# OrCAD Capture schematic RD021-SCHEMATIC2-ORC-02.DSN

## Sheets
1 5: size A3
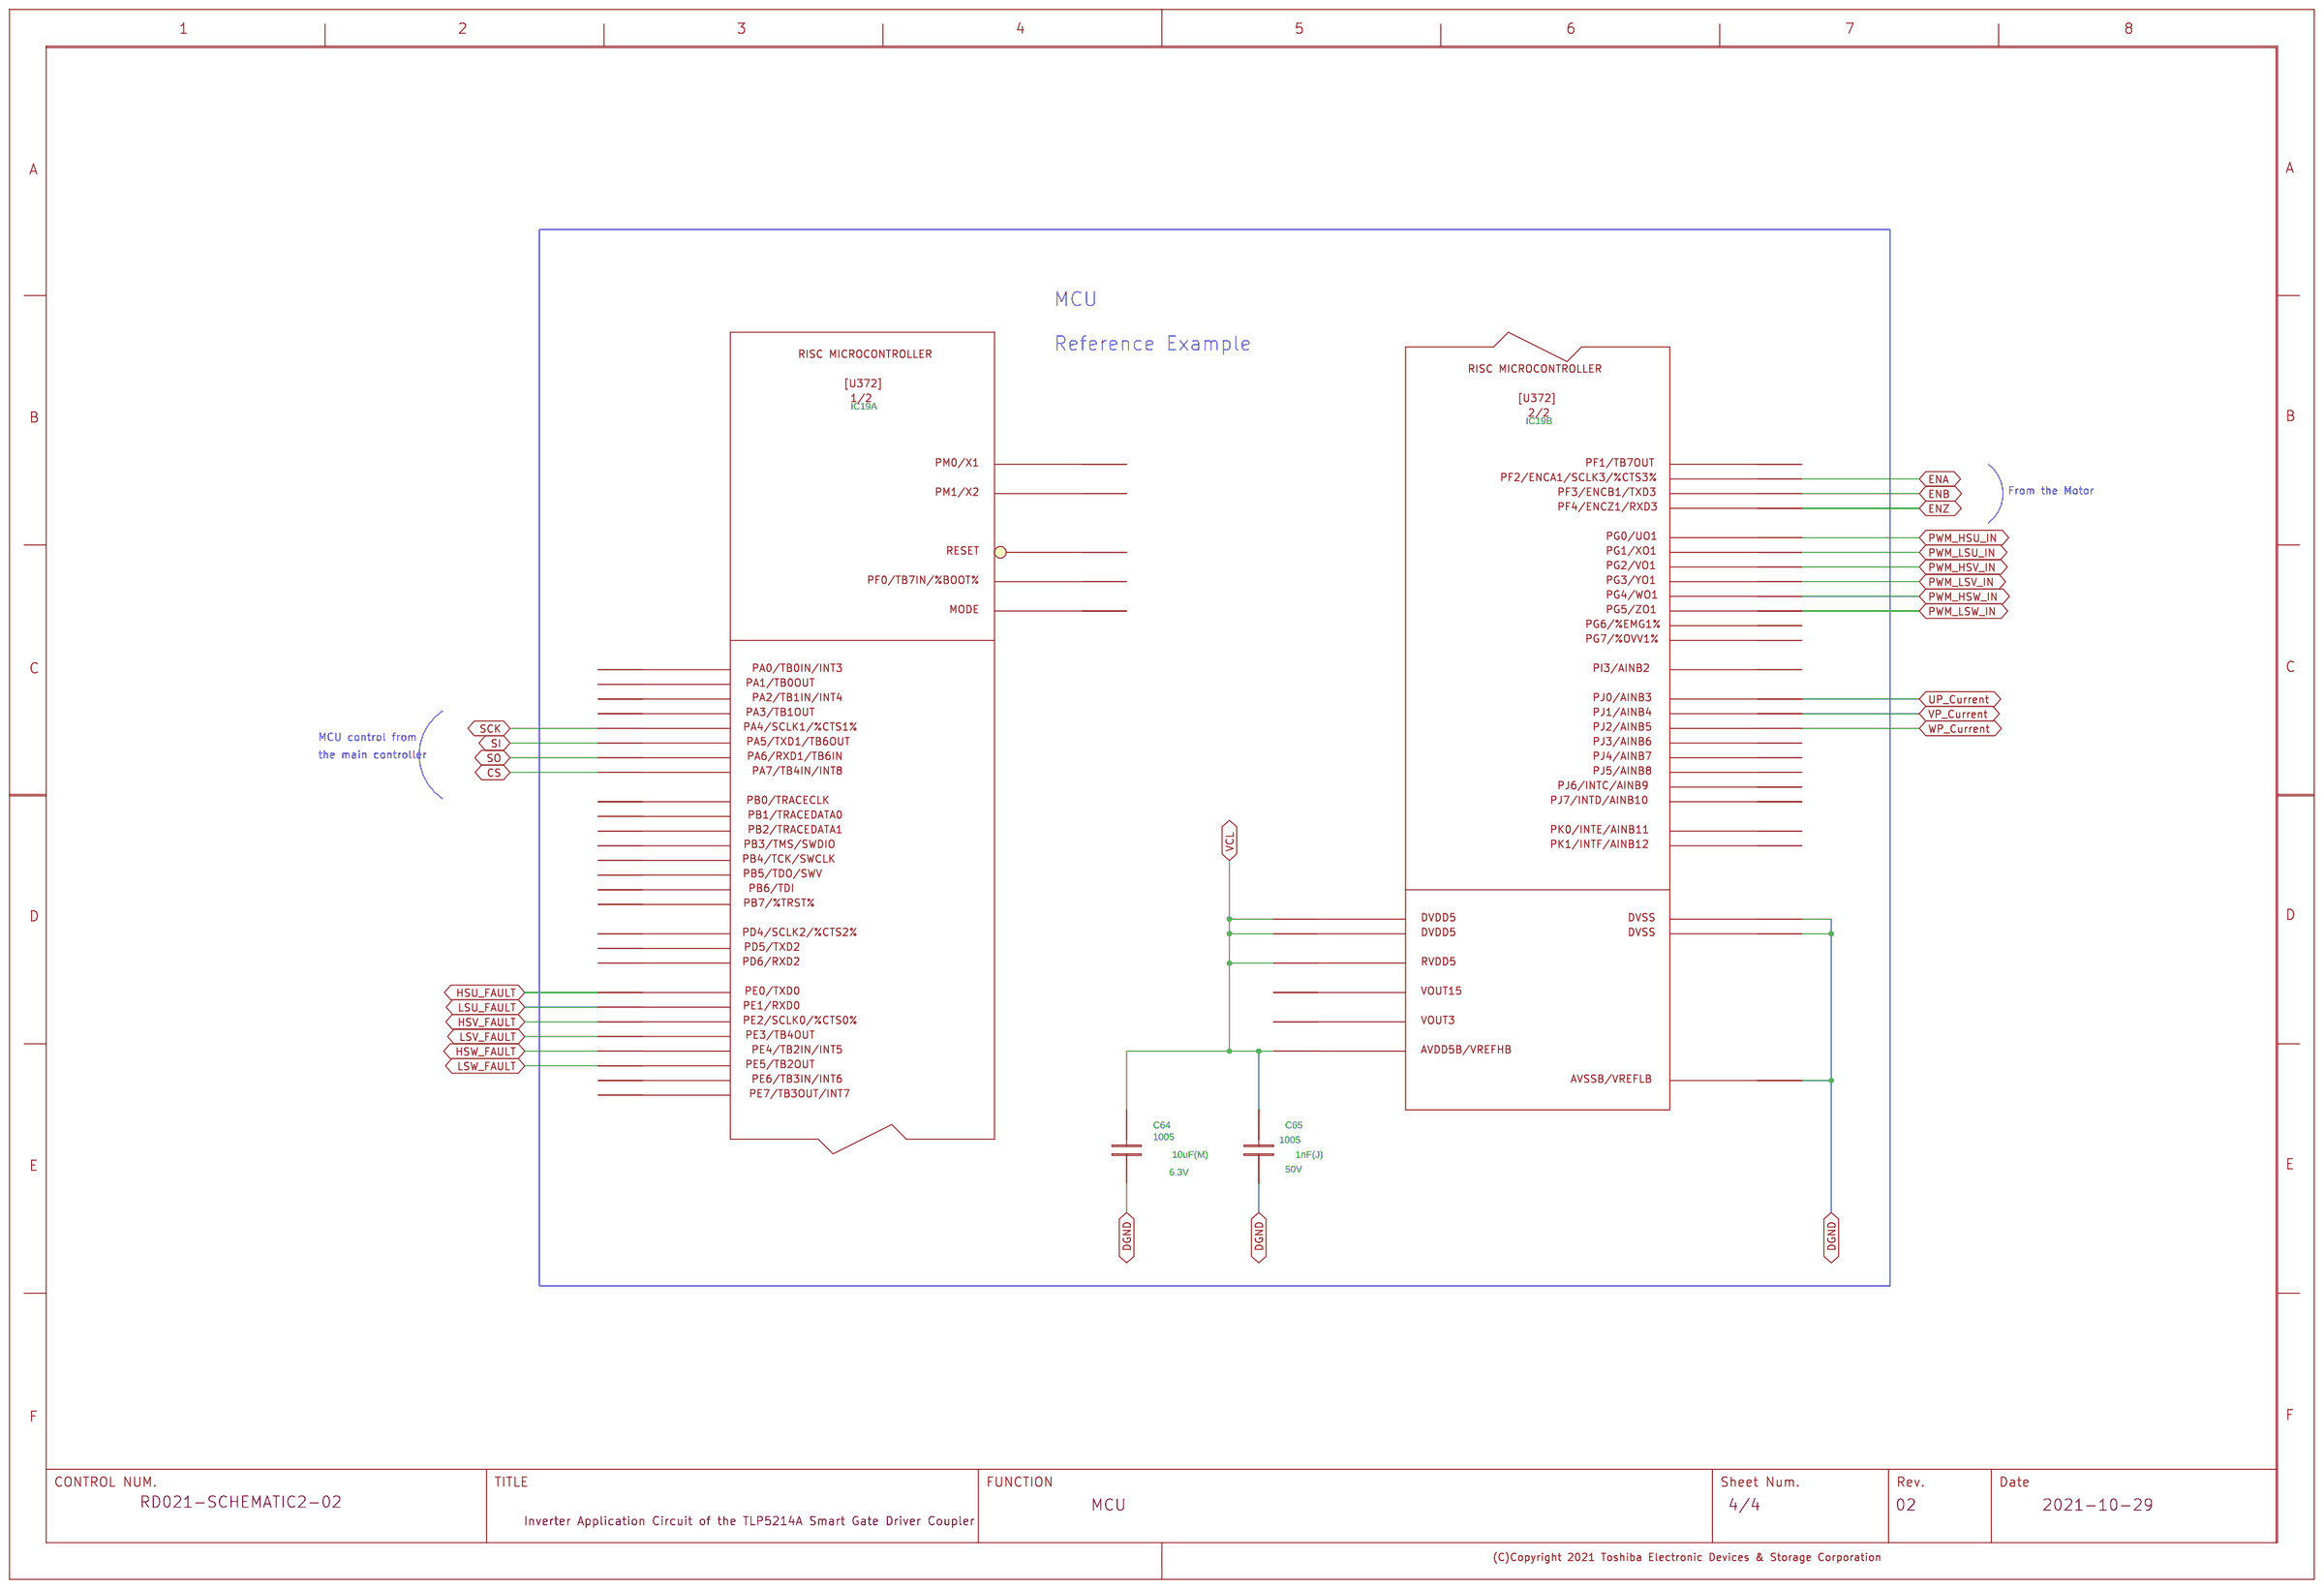
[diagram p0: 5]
2 4: size A3
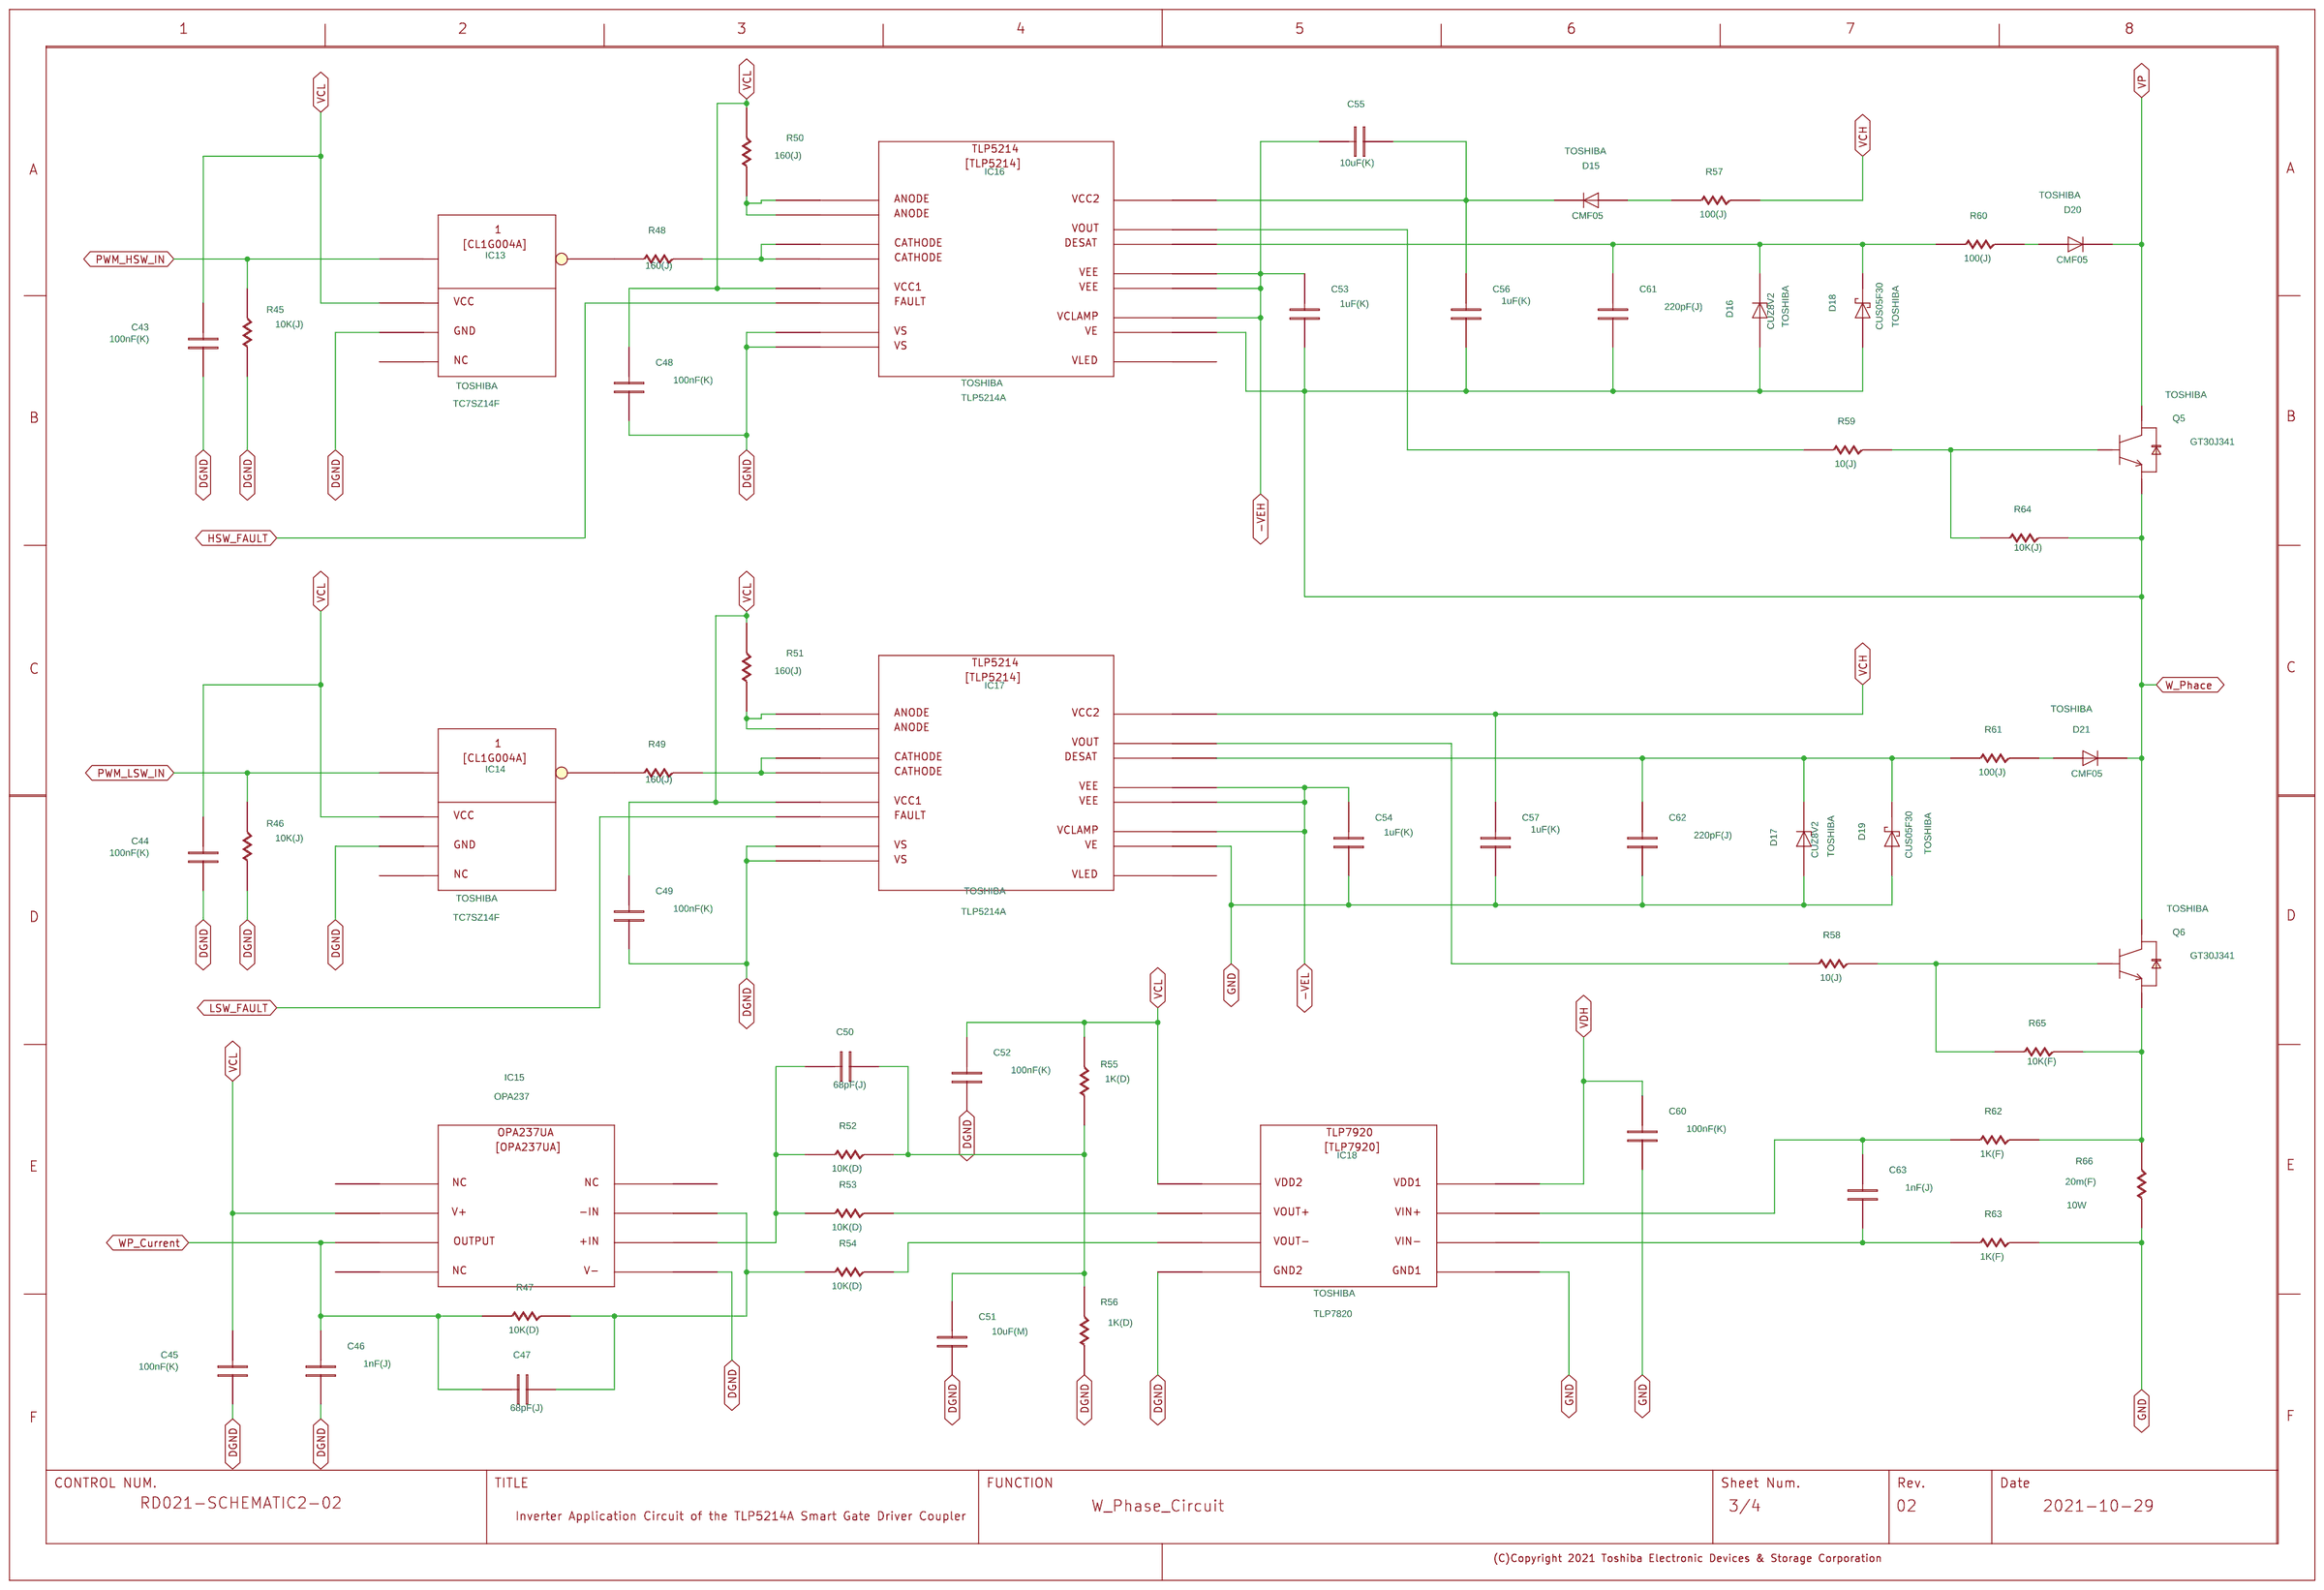
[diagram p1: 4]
3 3: size A3
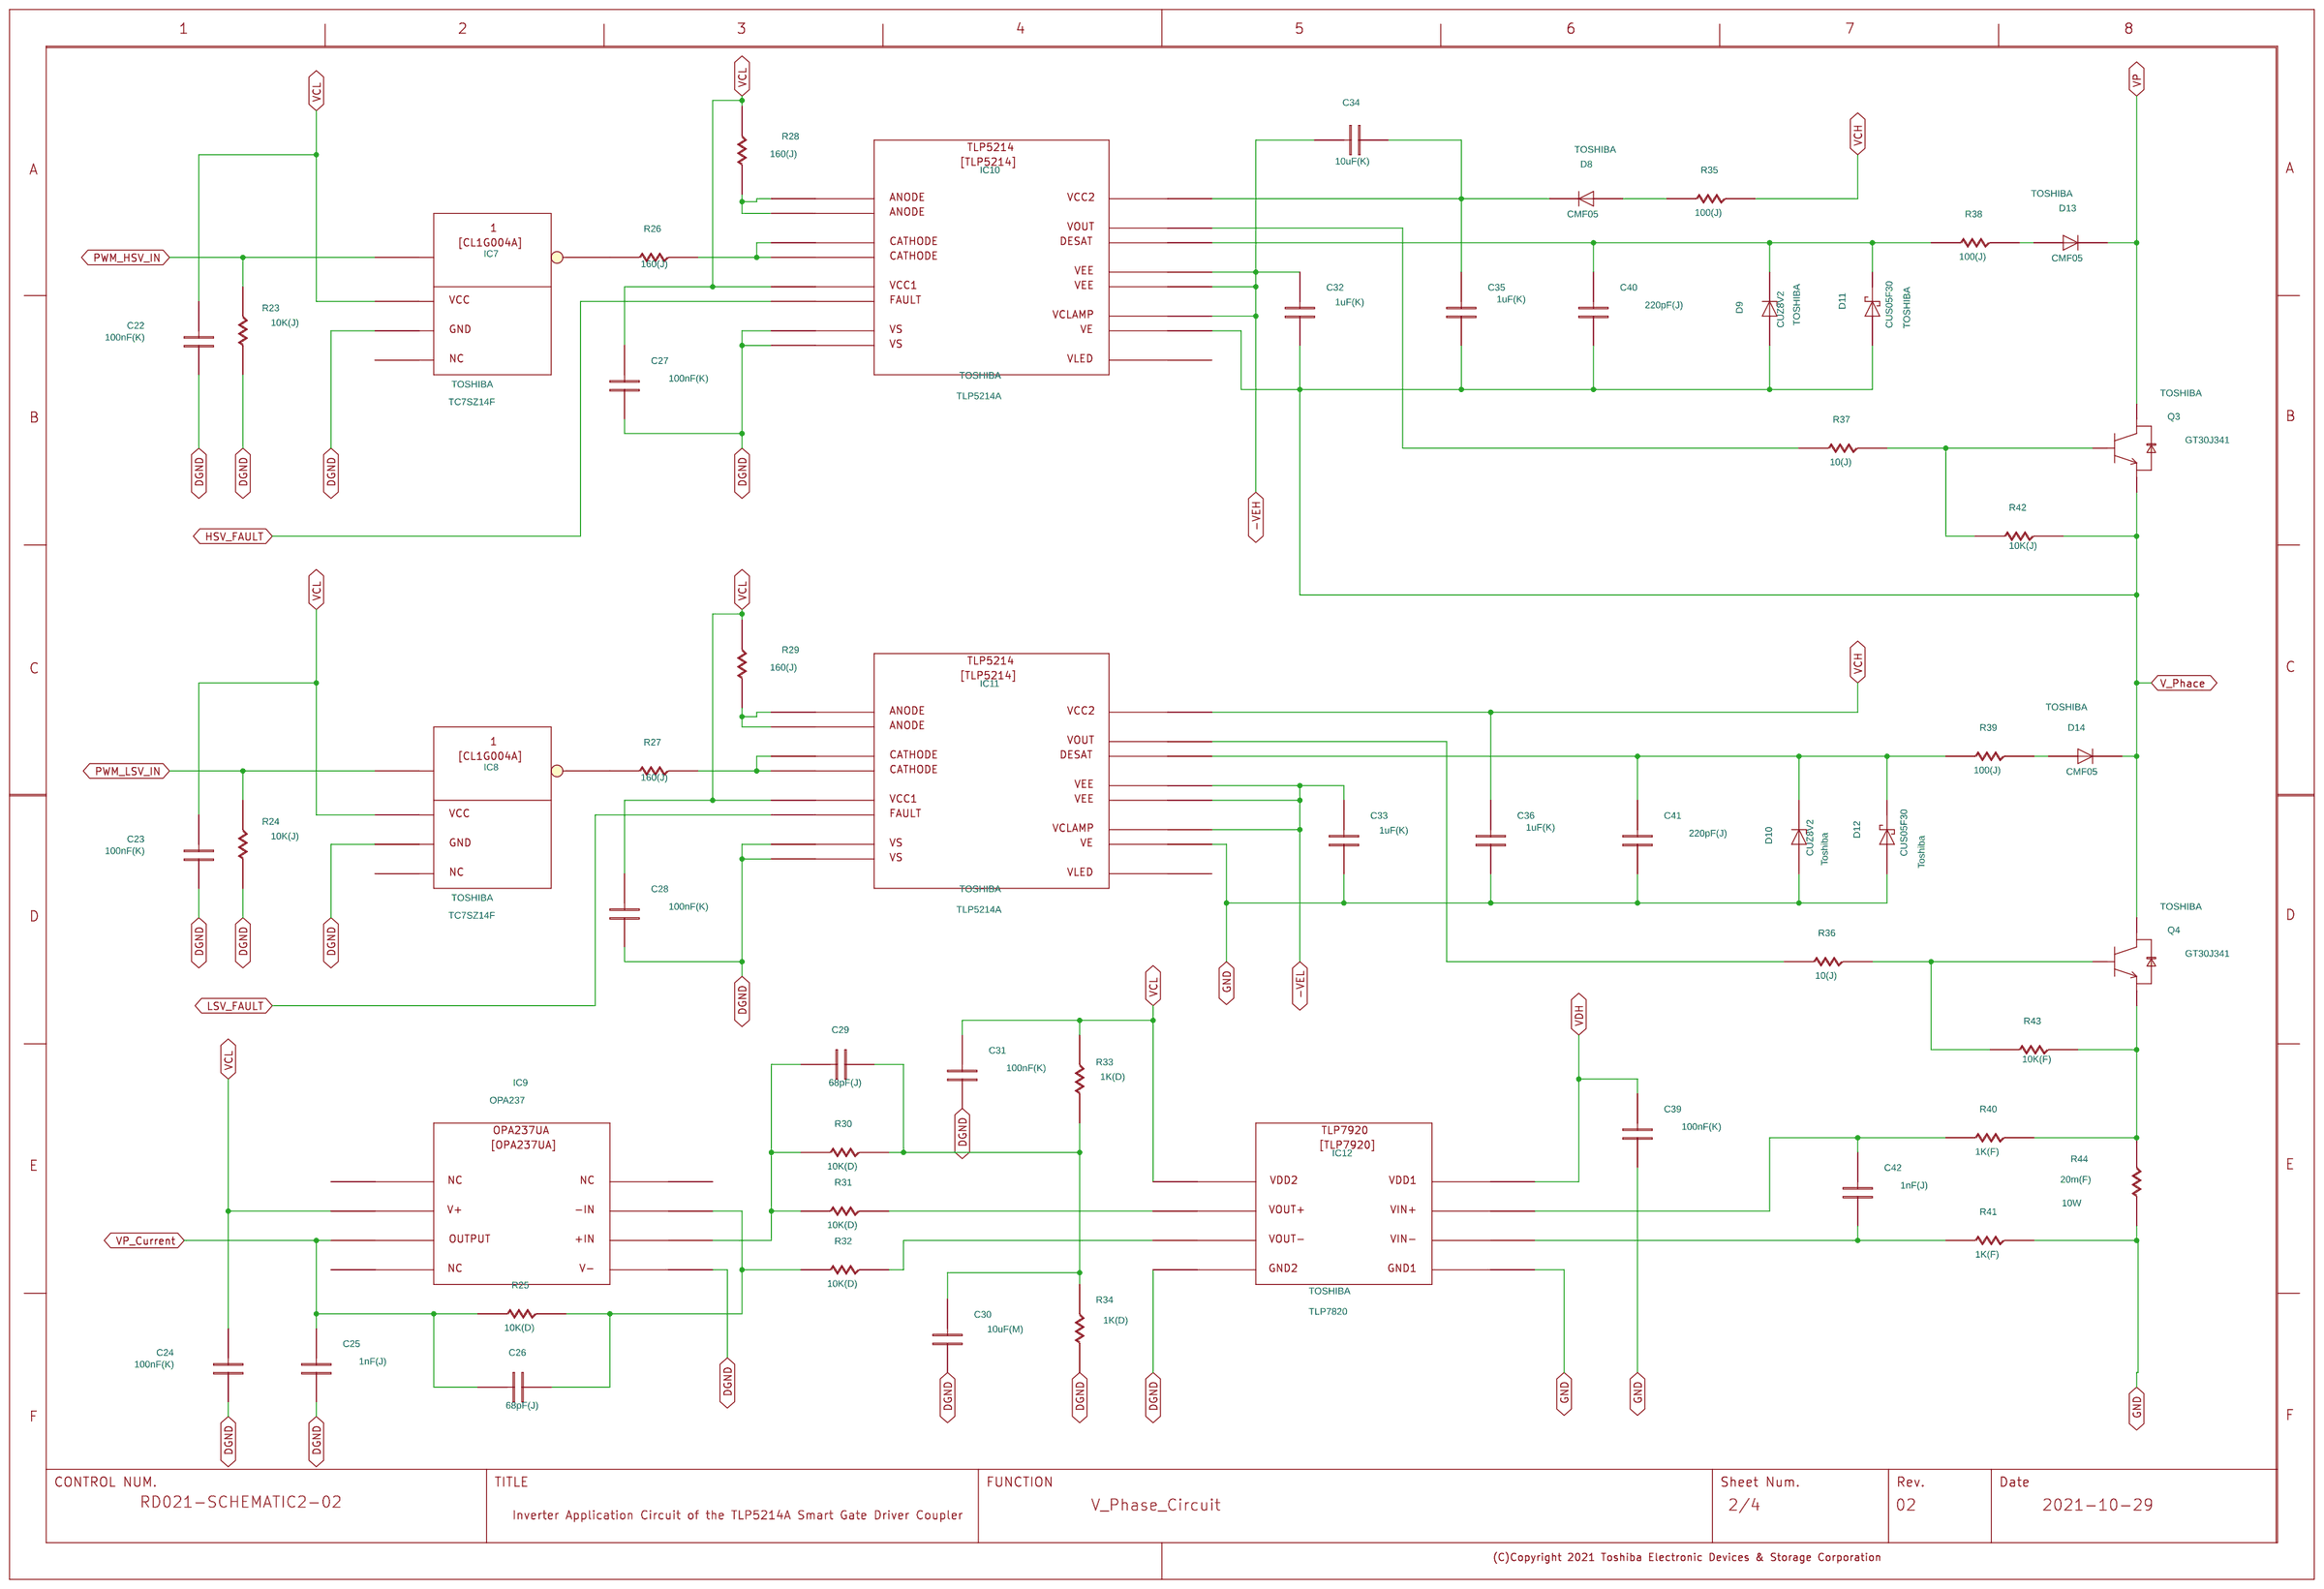
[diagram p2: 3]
4 2: size A3
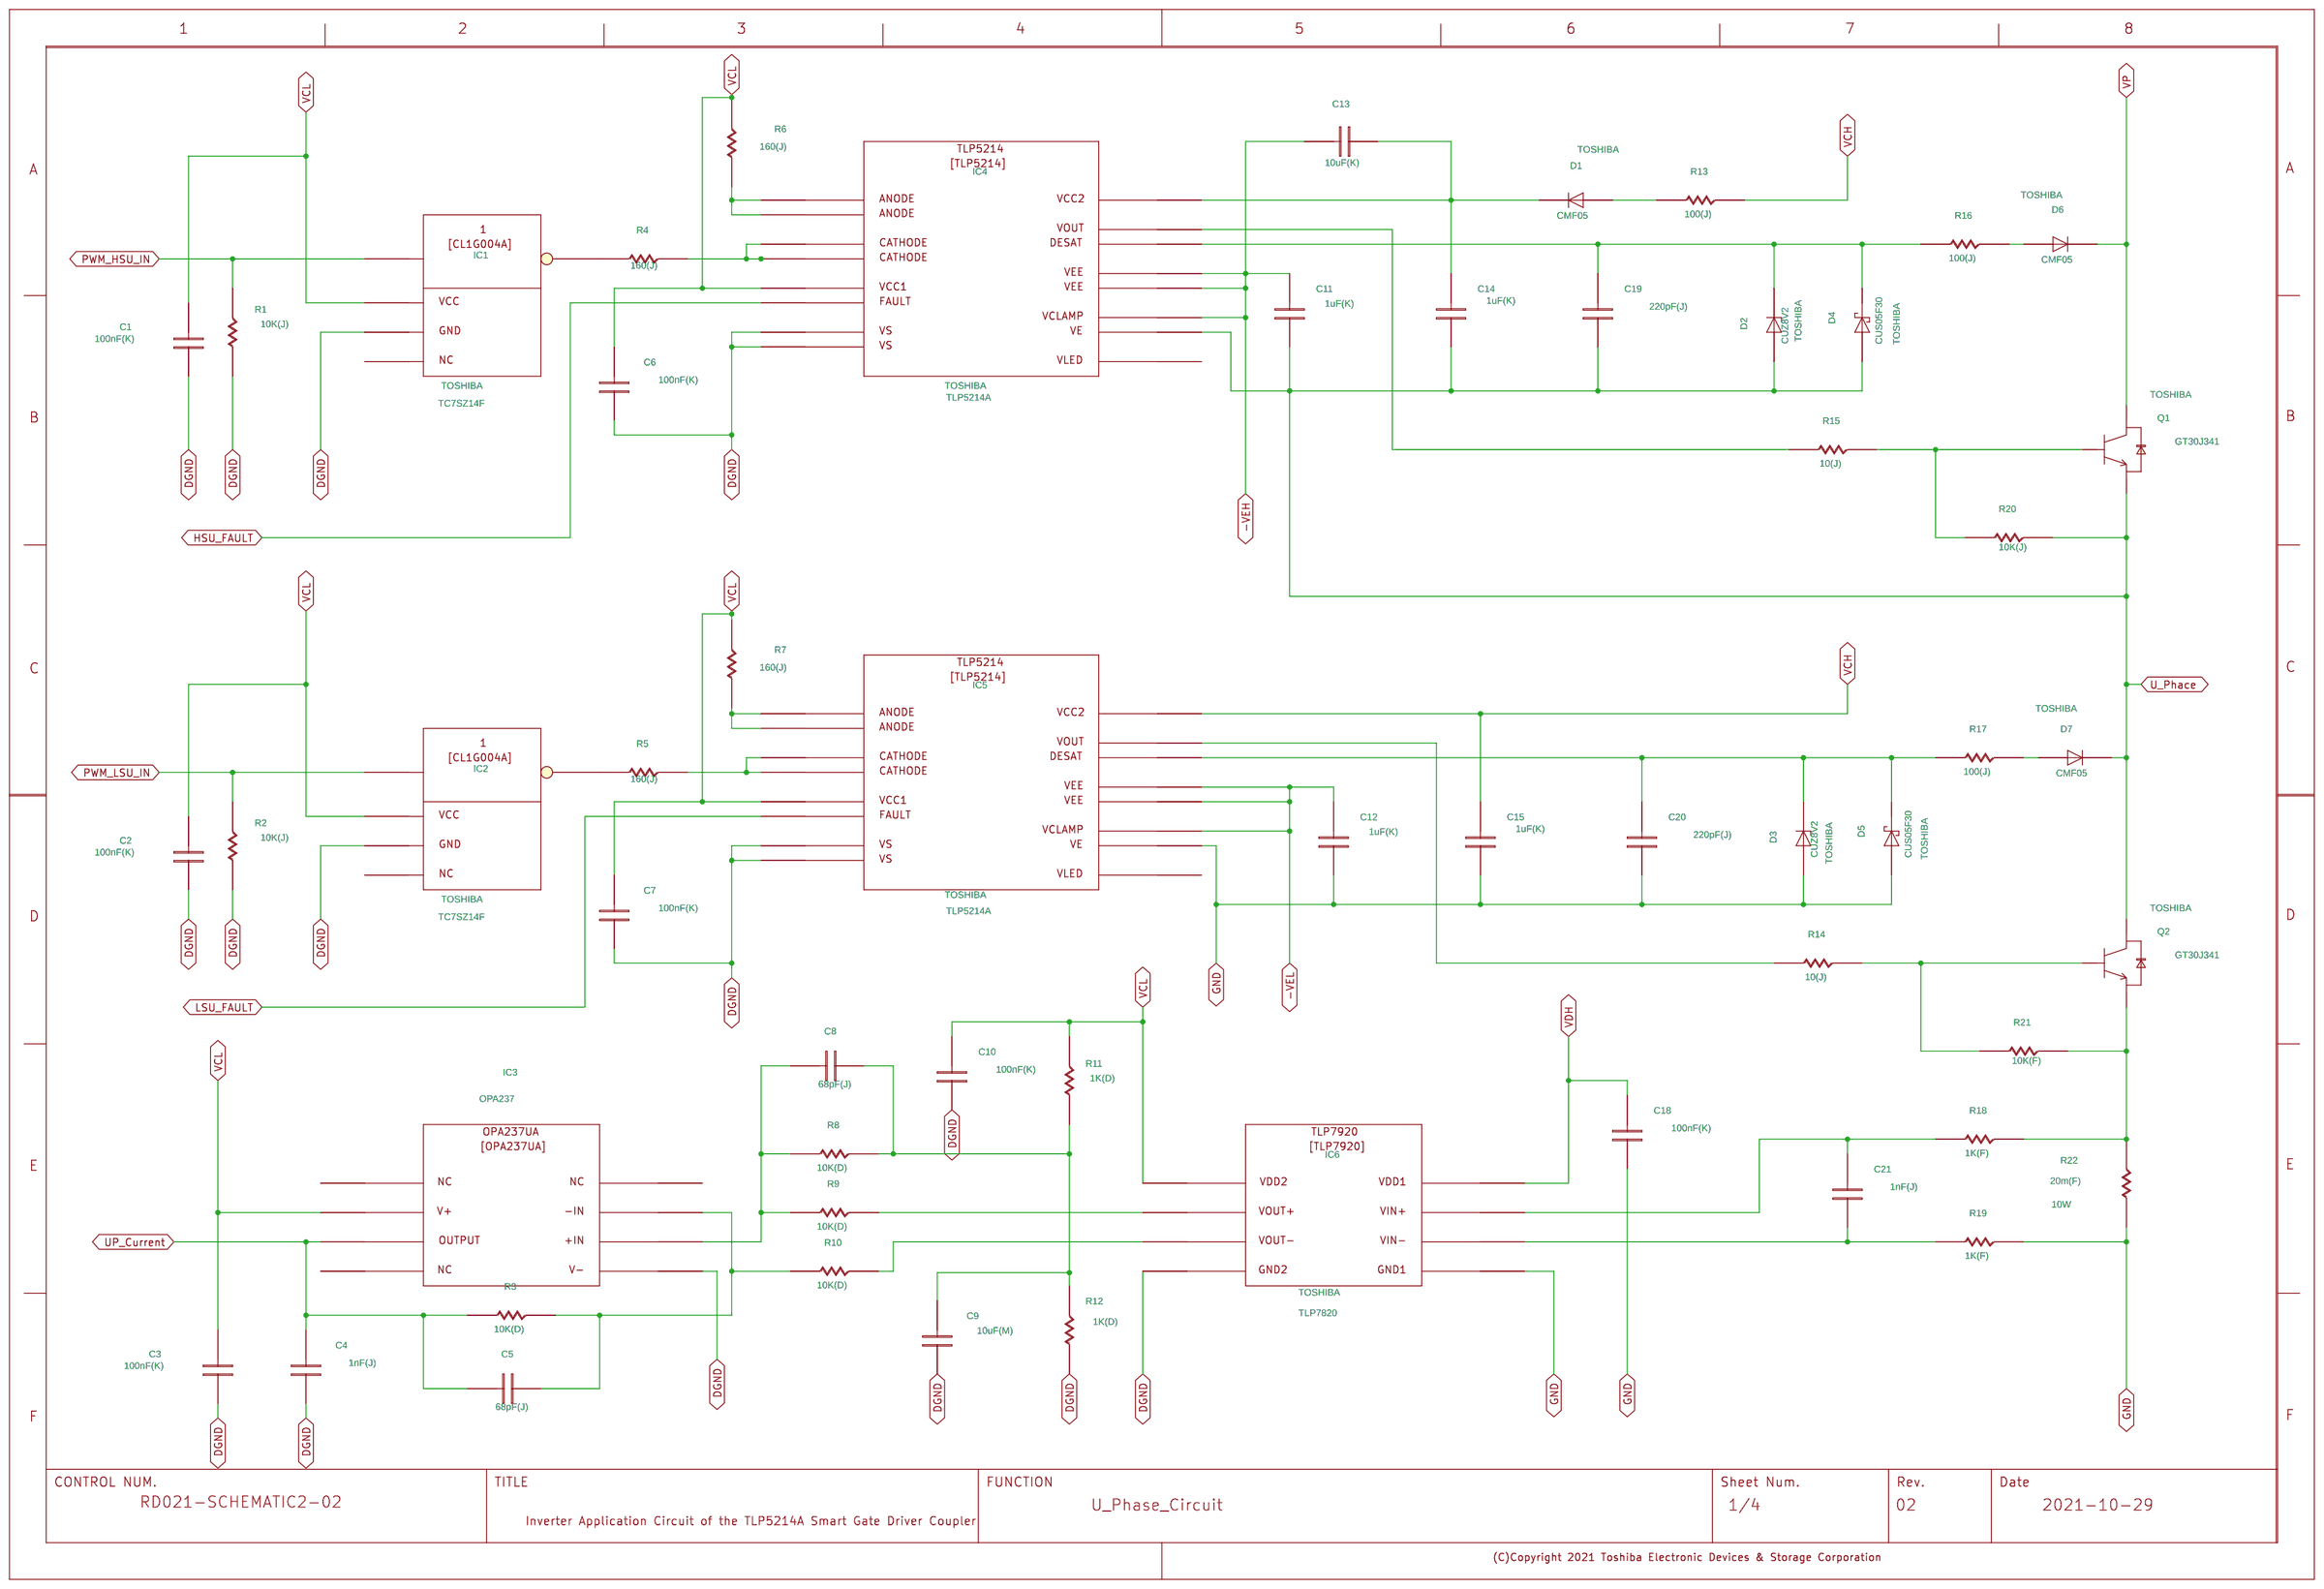
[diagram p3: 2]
5 1
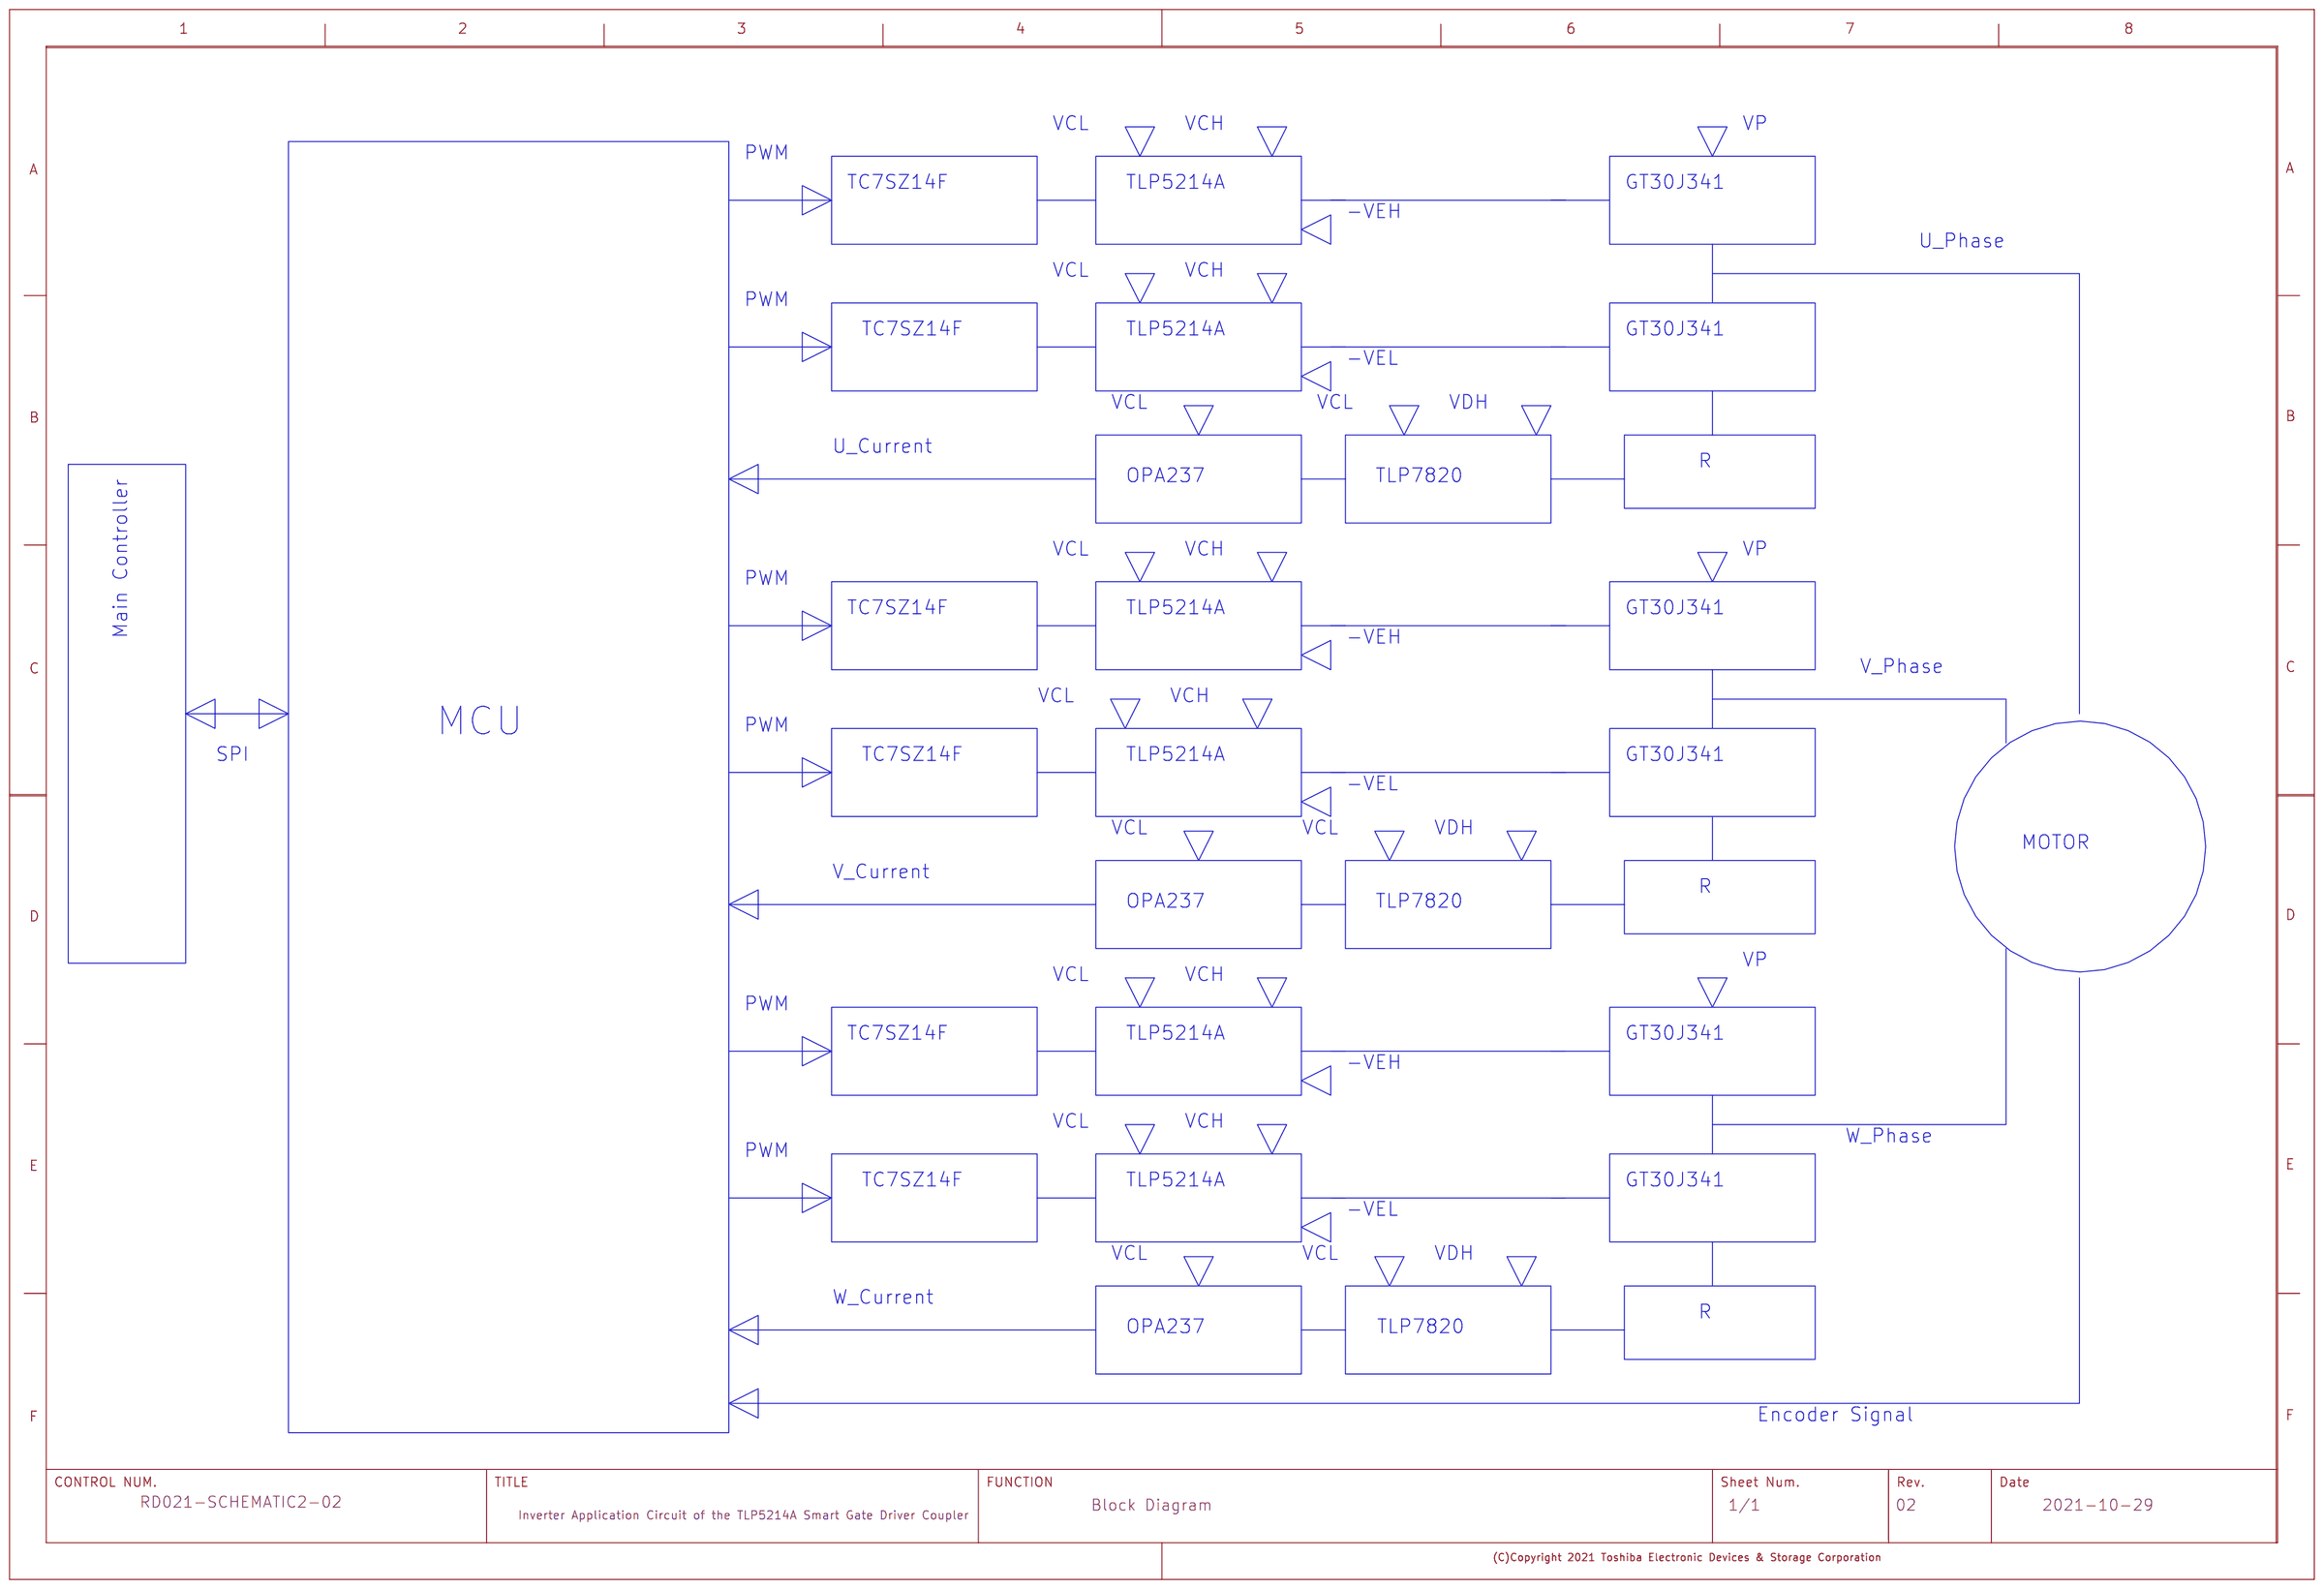
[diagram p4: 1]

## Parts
sheet 1
U?#4  WAKU_DEF100
sheet 2
C1  C
C2  C
C3  C
C4  C
C5  C
C6  C
C7  C
C8  C
C9  C
C10  C
C11  C
C12  C
C13  C
C14  C
C15  C
C18  C
C19  C
C20  C
C21  C
D1  D
D2  ZD
D3  ZD
D4  SBD
D5  SBD
D6  D
D7  D
IC1  CL1G004A
IC2  CL1G004A
IC3  S-OPA237UA
IC4  S-TLP5214
IC5  S-TLP5214
IC6  S-TLP7920
Q1  S-GT30J341
Q2  S-GT30J341
R1  R
R2  R
R3  R
R4  R
R5  R
R6  R
R7  R
R8  R
R9  R
R10  R
R11  R
R12  R
R13  R
R14  R
R15  R
R16  R
R17  R
R18  R
R19  R
R20  R
R21  R
R22  R
U?#3  WAKU_DEF100
sheet 3
C22  C
C23  C
C24  C
C25  C
C26  C
C27  C
C28  C
C29  C
C30  C
C31  C
C32  C
C33  C
C34  C
C35  C
C36  C
C39  C
C40  C
C41  C
C42  C
D8  D
D9  ZD
D10  ZD
D11  SBD
D12  SBD
D13  D
D14  D
IC7  CL1G004A
IC8  CL1G004A
IC9  S-OPA237UA
IC10  S-TLP5214
IC11  S-TLP5214
IC12  S-TLP7920
Q3  S-GT30J341
Q4  S-GT30J341
R23  R
R24  R
R25  R
R26  R
R27  R
R28  R
R29  R
R30  R
R31  R
R32  R
R33  R
R34  R
R35  R
R36  R
R37  R
R38  R
R39  R
R40  R
R41  R
R42  R
R43  R
R44  R
U?#2  WAKU_DEF100
sheet 4
C43  C
C44  C
C45  C
C46  C
C47  C
C48  C
C49  C
C50  C
C51  C
C52  C
C53  C
C54  C
C55  C
C56  C
C57  C
C60  C
C61  C
C62  C
C63  C
D15  D
D16  ZD
D17  ZD
D18  SBD
D19  SBD
D20  D
D21  D
IC13  CL1G004A
IC14  CL1G004A
IC15  S-OPA237UA
IC16  S-TLP5214
IC17  S-TLP5214
IC18  S-TLP7920
Q5  S-GT30J341
Q6  S-GT30J341
R45  R
R46  R
R47  R
R48  R
R49  R
R50  R
R51  R
R52  R
R53  R
R54  R
R55  R
R56  R
R57  R
R58  R
R59  R
R60  R
R61  R
R62  R
R63  R
R64  R
R65  R
R66  R
U?#1  WAKU_DEF100
sheet 5
C64  C
C65  C
IC19  U372_1  (sections A,B)
U?#5  WAKU_DEF100

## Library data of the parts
U?#4 = WAKU_DEF100_0: COMPONENTTYPE: 2; DATE: 2021-10-29; DRAWINGNUMBER: RD021-SCHEMATIC2-02; FUNCTION: Block Diagram; REVISION: 02; SHEETNUMBER: 1/1; TITLE: Inverter Application Circuit of the TLP5214A Smart Gate Driver Coupler; UPDATEDATE: 2018/06/19; UPDATETIME: 16:54:06; UPDATEUSER: g4302510
C1-C3 C6 C7 C10 C18 C22-C24 C27 C28 C31 C39 C43-C45 C48 C49 C52 C60 = C: ADSCNVFLAG: ON; ALLGREEN: 0:O[; CAPACITANCETOLE: K; CDBNAME: K0302394; CDMASTERCADCELG: KC0008; COMP: K0302394; COMPONENTNAME: K0302394_package; COMPONENTTYPE: 4; FNAPPROVALRESUG: 5:bè(KR[h); FNCANCELLATIONG: 0:Žg—p‰Â; FNENVIRONMANTRG: 0:Žg—p–³; FNLEADFREETHET1GT2GMCTH1: 3_2_N; FUNCN: K0302394; GANSWERREV: 9; GCOUNT: 1; ICX_PART_MODEL: CON_100N; MAXGCOUNT: 1; NOMINALCAPACITA: 100n; OUMECLASSIFICATION: ƒZƒ‰ƒ~ƒbƒNƒRƒ“ƒfƒ“ƒT; PMPRODUCTSTYPEG: HD1; QUADMODEL: CON_100N; RATEDVOLTAGE: 50; SIZECODESMD: 1608; SQ_PART_MODEL: CON_100N; VAL1: 100nF(K); VAL2: 50V
C4 C21 C25 C42 C46 C63 = C: ADSCNVFLAG: ON; ALLGREEN: N:¢²¸; CAPACITANCETOLE: J; CDBNAME: K0301613; CDMASTERCADCELG: KC0008; COMP: K0301613; COMPONENTNAME: K0301613_package; COMPONENTTYPE: 4; FNAPPROVALRESUG: 5:bè(KR[h); FNCANCELLATIONG: 0:Žg—p‰Â; FNENVIRONMANTRG: N:¢²¸; FNLEADFREETHET1GT2GMCTH1: N_N_N; FUNCN: K0301613; GCOUNT: 1; ICX_PART_MODEL: CON_1N; MAXGCOUNT: 1; NOMINALCAPACITA: 1n; OUMECLASSIFICATION: ƒZƒ‰ƒ~ƒbƒNƒRƒ“ƒfƒ“ƒT; PMPRODUCTSTYPEG: DME; QUADMODEL: CON_1N; RATEDVOLTAGE: 50; SIZECODESMD: 1608; SQ_PART_MODEL: CON_1N; VAL1: 1nF(J); VAL2: 50V
C5 C8 C26 C29 C47 C50 = C: ADSCNVFLAG: ON; ADSCOMPONENTNAME: C_1005; ADSMODELNAME: s_GRM1552C1H680JA01D; ALLGREEN: N:¢²¸; CAPACITANCETOLE: J; CDBNAME: GDM030002286; CDMASTERCADCELG: KC0005; COMP: GDM030002286; COMPONENTNAME: GDM030002286_package; COMPONENTTYPE: 4; FNAPPROVALRESUG: 0:”­”Ô‚Ì‚Ý; FNCANCELLATIONG: 0:Žg—p‰Â; FNENVIRONMANTRG: N:¢²¸; FNLEADFREETHET1GT2GMCTH1: N_N_N; FUNCN: GDM030002286; GCOUNT: 1; ICX_PART_MODEL: CON_68P; MAXGCOUNT: 1; NOMINALCAPACITA: 68p; OUMECLASSIFICATION: ƒZƒ‰ƒ~ƒbƒNƒRƒ“ƒfƒ“ƒT; OUMEMAKER: MRT ºc»ì; OUMEMAKERKATAMEI: GRM1552C1H680JA01D; PMPRODUCTSTYPEG: PC3; QUADMODEL: CON_68P; RATEDVOLTAGE: 50; SIZECODESMD: 1005; SQ_PART_MODEL: CON_68P; TEMPCHARACTERI2: CH; VAL1: 68pF(J); VAL2: 50V; VAL3: GRM1552C1H680JA01D
C9 C30 C51 = C: ADSCNVFLAG: ON; ADSCOMPONENTNAME: C_1608; ADSMODELNAME: s_ZRB18AR61E106ME01L; ALLGREEN: N:¢²¸; CAPACITANCETOLE: M; CDBNAME: K0302927; CDMASTERCADCELG: KC0167; COMP: K0302927; COMPONENTNAME: K0302927_package; COMPONENTTYPE: 4; FNAPPROVALRESUG: 5:bè(KR[h); FNCANCELLATIONG: 0:Žg—p‰Â; FNENVIRONMANTRG: N:¢²¸; FNLEADFREETHET1GT2GMCTH1: N_N_N; FUNCN: K0302927; GCOUNT: 1; ICX_PART_MODEL: CON_10U; MAXGCOUNT: 1; NOMINALCAPACITA: 10u; OUMECLASSIFICATION: ƒZƒ‰ƒ~ƒbƒNƒRƒ“ƒfƒ“ƒT; OUMEMAKER: MRT ºc»ì; OUMEMAKERKATAMEI: ZRB18AR61E106ME01L; QUADMODEL: CON_10U; RATEDVOLTAGE: 25; SIZECODESMD: 1608; SQ_PART_MODEL: CON_10U; VAL1: 10uF(M); VAL2: 25V; VAL3: ZRB18AR61E106ME01L
C11 C12 C14 C15 C32 C33 C35 C36 C53 C54 C56 C57 = C: ADSCNVFLAG: ON; ADSCOMPONENTNAME: C_2012; ADSMODELNAME: s_GCM21BR71H105KA01L@@; ALLGREEN: N:¢²¸; CAPACITANCETOLE: K; CDBNAME: K0302742; CDMASTERCADCELG: KC0136; COMP: K0302742; COMPONENTNAME: K0302742_package; COMPONENTTYPE: 4; FNAPPROVALRESUG: 5:bè(KR[h); FNCANCELLATIONG: 0:Žg—p‰Â; FNENVIRONMANTRG: N:¢²¸; FNLEADFREETHET1GT2GMCTH1: N_N_N; FUNCN: K0302742; GCOUNT: 1; ICX_PART_MODEL: CON_1U; MAXGCOUNT: 1; NOMINALCAPACITA: 1u; OUMECLASSIFICATION: ƒZƒ‰ƒ~ƒbƒNƒRƒ“ƒfƒ“ƒT; OUMEMAKER: MRT ºc»ì; OUMEMAKERKATAMEI: GCM21BR71H105KA01L@@; QUADMODEL: CON_1U; RATEDVOLTAGE: 50; SIZECODESMD: 2012; SQ_PART_MODEL: CON_1U; VAL1: 1uF(K); VAL2: 50V; VAL3: GCM21BR71H105KA01L@@
C13 C34 C55 = C: ADSCNVFLAG: ON; ADSCOMPONENTNAME: C_2012; ADSMODELNAME: s_C2012JB0J106K085AB; ALLGREEN: N:¢²¸; CAPACITANCETOLE: K; CDBNAME: K0302650; CDMASTERCADCELG: KC0006; COMP: K0302650; COMPONENTNAME: K0302650_package; COMPONENTTYPE: 4; FNAPPROVALRESUG: 5:bè(KR[h); FNCANCELLATIONG: 0:Žg—p‰Â; FNENVIRONMANTRG: N:¢²¸; FNLEADFREETHET1GT2GMCTH1: N_N_N; FUNCN: K0302650; GCOUNT: 1; ICX_PART_MODEL: CON_10U; MAXGCOUNT: 1; NOMINALCAPACITA: 10u; OUMECLASSIFICATION: ƒZƒ‰ƒ~ƒbƒNƒRƒ“ƒfƒ“ƒT; OUMEMAKER: TDK ‚s‚c‚j; OUMEMAKERKATAMEI: C2012JB0J106K085AB; QUADMODEL: CON_10U; RATEDVOLTAGE: 6.3; SIZECODESMD: 2012; SQ_PART_MODEL: CON_10U; TEMPCHARACTERI2: B; VAL1: 10uF(K); VAL2: 6.3V; VAL3: C2012JB0J106K085AB
C19 C20 C40 C41 C61 C62 = C: ADSCNVFLAG: ON; ALLGREEN: N:¢²¸; CAPACITANCETOLE: J; CDBNAME: K0301642; CDMASTERCADCELG: KC0008; COMP: K0301642; COMPONENTNAME: K0301642_package; COMPONENTTYPE: 4; FNAPPROVALRESUG: 5:bè(KR[h); FNCANCELLATIONG: 0:Žg—p‰Â; FNENVIRONMANTRG: N:¢²¸; FNLEADFREETHET1GT2GMCTH1: N_N_N; FUNCN: K0301642; GCOUNT: 1; ICX_PART_MODEL: CON_220P; MAXGCOUNT: 1; NOMINALCAPACITA: 220p; OUMECLASSIFICATION: ƒZƒ‰ƒ~ƒbƒNƒRƒ“ƒfƒ“ƒT; PMPRODUCTSTYPEG: DME; QUADMODEL: CON_220P; RATEDVOLTAGE: 50; SIZECODESMD: 1608; SQ_PART_MODEL: CON_220P; VAL1: 220pF(J); VAL2: 50V
D1 D6-D8 D13-D15 D20 D21 = D: COMPONENTTYPE: 4; VAL1: CMF05; VAL2: TOSHIBA
D2 D3 D9 D16 D17 = ZD: COMPONENTTYPE: 4; VAL1: CUZ8V2; VAL2: TOSHIBA
D4 D5 D11 D18 D19 = SBD: COMPONENTTYPE: 4; VAL1: CUS05F30; VAL2: TOSHIBA
IC1 IC2 IC7 IC8 IC13 IC14 = CL1G004A: ADSCNVFLAG: ON; ALLGREEN: N:¢²¸; CDBNAME: K4501373; CDMASTERCADCELG: MM0212; COMP: K4501373; COMPONENTNAME: K4501373_package; COMPONENTTYPE: 4; FNAPPROVALRESUG: 5:bè(KR[h); FNCANCELLATIONG: 0:Žg—p‰Â; FNENVIRONMANTRG: N:¢²¸; FNLEADFREETHET1GT2GMCTH1: N_N_N; FUNCN: K4501373; GCOUNT: 1; MAXGCOUNT: 1; MOUNTINGFORMSMD: SMD; OUMECLASSIFICATION: CMOSWbN; OUMEMAKER: TSB “ŒŽÅ; OUMEMAKERKATAMEI: TC7SZ04AFS; OUMEPARTTYPE: IC; PROCESS: 74LCX; USERCOMPTEXT1: TOSHIBA; VAL1: TC7SZ14F; VAL3: TC7SZ04AFS
IC3 IC9 IC15 = S-OPA237UA: COMPONENTTYPE: 4; USERCOMPTEXT1: OPA237
IC4 IC5 IC10 IC11 IC16 IC17 = S-TLP5214: COMPONENTTYPE: 4; USERCOMPTEXT1: TOSHIBA; USERCOMPTEXT2: TLP5214A
IC6 IC12 IC18 = S-TLP7920: COMPONENTTYPE: 4; USERCOMPTEXT1: TOSHIBA; USERCOMPTEXT2: TLP7820
Q1-Q6 = S-GT30J341: COMPONENTTYPE: 4; VAL1: GT30J341; VAL2: TOSHIBA
R1 R2 R23 R24 R45 R46 = R: ADSCNVFLAG: ON; ADSCOMPONENTNAME: R_1608; ADSMODELNAME: s_RK73B1JTTD103J@@; ALLGREEN: N:¢²¸; CDBNAME: K0104129; CDMASTERCADCELG: KC0133; COMP: K0104129; COMPONENTNAME: K0104129_package; COMPONENTTYPE: 4; FNAPPROVALRESUG: 5:bè(KR[h); FNCANCELLATIONG: 0:Žg—p‰Â; FNENVIRONMANTRG: N:¢²¸; FNLEADFREETHET1GT2GMCTH1: N_N_N; FUNCN: K0104129; GCOUNT: 1; ICX_PART_MODEL: RES_10K; MAXGCOUNT: 1; MOUNTINGFORMSMD: SMD; NOMINALRESISTAN: 10K; OUMECLASSIFICATION: \ÊÀpÅèïRí; OUMEMAKER: KOA R[A; OUMEMAKERKATAMEI: RK73B1JTTD103J@@; POWERRATING: 100m; QUADMODEL: RES_10K; RESISTANCETOLER: J; SIZECODESMD: 1608; SQ_PART_MODEL: RES_10K; VAL1: 10K(J); VAL2: 100mW; VAL3: RK73B1JTTD103J@@
R3 R8-R10 R25 R30-R32 R47 R52-R54 = R: ADSCNVFLAG: ON; ADSCOMPONENTNAME: R_1608; ADSMODELNAME: s_RK73B1JTTD103J@@; ALLGREEN: N:¢²¸; CDBNAME: K0104129; CDMASTERCADCELG: KC0133; COMP: K0104129; COMPONENTNAME: K0104129_package; COMPONENTTYPE: 4; FNAPPROVALRESUG: 5:bè(KR[h); FNCANCELLATIONG: 0:Žg—p‰Â; FNENVIRONMANTRG: N:¢²¸; FNLEADFREETHET1GT2GMCTH1: N_N_N; FUNCN: K0104129; GCOUNT: 1; ICX_PART_MODEL: RES_10K; MAXGCOUNT: 1; MOUNTINGFORMSMD: SMD; NOMINALRESISTAN: 10K; OUMECLASSIFICATION: \ÊÀpÅèïRí; OUMEMAKER: KOA R[A; OUMEMAKERKATAMEI: RK73B1JTTD103J@@; POWERRATING: 100m; QUADMODEL: RES_10K; RESISTANCETOLER: J; SIZECODESMD: 1608; SQ_PART_MODEL: RES_10K; VAL1: 10K(D); VAL2: 100mW; VAL3: RK73B1JTTD103J@@
R4-R7 R26-R29 R48-R51 = R: ADSCNVFLAG: ON; ADSCOMPONENTNAME: R_1608; ADSMODELNAME: s_ERJ3GEYJ331V; ALLGREEN: 0:O[; CDBNAME: GDM010001670; CDMASTERCADCELG: KC0008; COMP: GDM010001670; COMPONENTNAME: GDM010001670_package; COMPONENTTYPE: 4; FNAPPROVALRESUG: B:i(GREEN); FNCANCELLATIONG: 0:Žg—p‰Â; FNENVIRONMANTRG: 1:gpL(K§ÎÛO); FNLEADFREETHET1GT2GMCTH1: 3_1_N; FUNCN: GDM010001670; GANSWERREV: 6; GCOUNT: 1; ICX_PART_MODEL: RES_330; MAXGCOUNT: 1; MOUNTINGFORMSMD: SMD; NOMINALRESISTAN: 330; OUMECLASSIFICATION: \ÊÀpÅèïRí; OUMEMAKER: NAE pi\jbNGNgjbNfoCX; OUMEMAKERKATAMEI: ERJ3GEYJ331V; POWERRATING: 63m; QUADMODEL: RES_330; RESISTANCETOLER: J; SIZECODESMD: 1608; SQ_PART_MODEL: RES_330; VAL1: 160(J); VAL2: 63mW; VAL3: ERJ3GEYJ331V
R11 R12 R33 R34 R55 R56 = R: ADSCNVFLAG: ON; ALLGREEN: N:¢²¸; CDBNAME: K0102095; CDMASTERCADCELG: KC0008; COMP: K0102095; COMPONENTNAME: K0102095_package; COMPONENTTYPE: 4; FNAPPROVALRESUG: 5:bè(KR[h); FNCANCELLATIONG: 0:Žg—p‰Â; FNENVIRONMANTRG: N:¢²¸; FNLEADFREETHET1GT2GMCTH1: N_N_N; FUNCN: K0102095; GCOUNT: 1; ICX_PART_MODEL: RES_1K; MAXGCOUNT: 1; NOMINALRESISTAN: 1K; OUMECLASSIFICATION: \ÊÀpÅèïRí; PMPRODUCTSTYPEG: DME; POWERRATING: 100m; QUADMODEL: RES_1K; RESISTANCETOLER: D; SIZECODESMD: 1608; SQ_PART_MODEL: RES_1K; VAL1: 1K(D); VAL2: 100mW
R13 R16 R17 R35 R38 R39 R57 R60 R61 = R: ADSCNVFLAG: ON; ADSCOMPONENTNAME: R_2012; ADSMODELNAME: s_ERJP06J101V; ALLGREEN: 0:O[; CDBNAME: GDM010002461; CDMASTERCADCELG: KC0006; COMP: GDM010002461; COMPONENTNAME: GDM010002461_package; COMPONENTTYPE: 4; FNAPPROVALRESUG: B:i(GREEN); FNCANCELLATIONG: 0:Žg—p‰Â; FNENVIRONMANTRG: 1:gpL(K§ÎÛO); FNLEADFREETHET1GT2GMCTH1: 2_2_N; FUNCN: GDM010002461; GANSWERREV: 11; GCOUNT: 1; ICX_PART_MODEL: RES_100; MAXGCOUNT: 1; MOUNTINGFORMSMD: SMD; NOMINALRESISTAN: 100; OUMECLASSIFICATION: \ÊÀpÅèïRí; OUMEMAKER: NAE pi\jbNGNgjbNfoCX; OUMEMAKERKATAMEI: ERJP06J101V; PMPRODUCTSTYPEG: PC1-PCS; POWERRATING: 250m; QUADMODEL: RES_100; RESISTANCETOLER: J; SIZECODESMD: 2012; SQ_PART_MODEL: RES_100; VAL1: 100(J); VAL2: 250mW; VAL3: ERJP06J101V
R14 R15 R36 R37 R58 R59 = R: ADSCNVFLAG: ON; ADSCOMPONENTNAME: R_1608; ADSMODELNAME: s_RC0603JR_0710RL; ALLGREEN: 0:O[; CDBNAME: GDM010004404; CDMASTERCADCELG: KC0008; COMP: GDM010004404; COMPONENTNAME: GDM010004404_package; COMPONENTTYPE: 4; FNAPPROVALRESUG: B:i(GREEN); FNCANCELLATIONG: 0:Žg—p‰Â; FNENVIRONMANTRG: 1:gpL(K§ÎÛO); FNLEADFREETHET1GT2GMCTH1: 2_1_N; FUNCN: GDM010004404; GANSWERREV: 11; GCOUNT: 1; ICX_PART_MODEL: RES_10; MAXGCOUNT: 1; MOUNTINGFORMSMD: SMD; NOMINALRESISTAN: 10; OUMECLASSIFICATION: \ÊÀpÅèïRí; OUMEMAKER: YGO ƒ„ƒQƒI; OUMEMAKERKATAMEI: RC0603JR-0710RL; PMPRODUCTSTYPEG: DME-PC1; POWERRATING: 100m; QUADMODEL: RES_10; RESISTANCETOLER: J; SIZECODESMD: 1608; SQ_PART_MODEL: RES_10; VAL1: 10(J); VAL2: 100mW; VAL3: RC0603JR-0710RL
R18 R19 R40 R41 R62 R63 = R: ADSCNVFLAG: ON; ADSCOMPONENTNAME: R_1608; ADSMODELNAME: s_ERJ3GEYJ102V_; ALLGREEN: N:¢²¸; CDBNAME: K0102703; CDMASTERCADCELG: KCK0217; COMP: K0102703; COMPONENTNAME: K0102703_package; COMPONENTTYPE: 4; FNAPPROVALRESUG: 5:bè(KR[h); FNCANCELLATIONG: 0:Žg—p‰Â; FNENVIRONMANTRG: N:¢²¸; FNLEADFREETHET1GT2GMCTH1: N_N_N; FUNCN: K0102703; GCOUNT: 1; ICX_PART_MODEL: RES_1K; MAXGCOUNT: 1; MOUNTINGFORMSMD: SMD; NOMINALRESISTAN: 1K; OUMECLASSIFICATION: \ÊÀpÅèïRí; OUMEMAKER: NAE pi\jbNGNgjbNfoCX; OUMEMAKERKATAMEI: ERJ3GEYJ102V.; POWERRATING: 100m; QUADMODEL: RES_1K; RESISTANCETOLER: J; SIZECODESMD: 1608; SQ_PART_MODEL: RES_1K; VAL1: 1K(F); VAL2: 100mW; VAL3: ERJ3GEYJ102V.
R20 R42 R64 = R: ADSCNVFLAG: ON; ADSCOMPONENTNAME: R_1608; ADSMODELNAME: s_RPC05T103F; ALLGREEN: N:¢²¸; CDBNAME: K0101879; CDMASTERCADCELG: KC0008; COMP: K0101879; COMPONENTNAME: K0101879_package; COMPONENTTYPE: 4; FNAPPROVALRESUG: 5:bè(KR[h); FNCANCELLATIONG: 0:Žg—p‰Â; FNENVIRONMANTRG: N:¢²¸; FNLEADFREETHET1GT2GMCTH1: N_N_N; FUNCN: K0101879; GCOUNT: 1; ICX_PART_MODEL: RES_10K; MAXGCOUNT: 1; MOUNTINGFORMSMD: SMD; NOMINALRESISTAN: 10K; OUMECLASSIFICATION: \ÊÀpÅèïRí; OUMEMAKER: TID ‘¾—zŽÐ“d‹C; OUMEMAKERKATAMEI: RPC05T103F; POWERRATING: 100m; QUADMODEL: RES_10K; RESISTANCETOLER: F; SIZECODESMD: 1608; SQ_PART_MODEL: RES_10K; VAL1: 10K(J); VAL2: 100mW; VAL3: RPC05T103F
R21 R43 R65 = R: ADSCNVFLAG: ON; ADSCOMPONENTNAME: R_1608; ADSMODELNAME: s_RPC05T103F; ALLGREEN: N:¢²¸; CDBNAME: K0101879; CDMASTERCADCELG: KC0008; COMP: K0101879; COMPONENTNAME: K0101879_package; COMPONENTTYPE: 4; FNAPPROVALRESUG: 5:bè(KR[h); FNCANCELLATIONG: 0:Žg—p‰Â; FNENVIRONMANTRG: N:¢²¸; FNLEADFREETHET1GT2GMCTH1: N_N_N; FUNCN: K0101879; GCOUNT: 1; ICX_PART_MODEL: RES_10K; MAXGCOUNT: 1; MOUNTINGFORMSMD: SMD; NOMINALRESISTAN: 10K; OUMECLASSIFICATION: \ÊÀpÅèïRí; OUMEMAKER: TID ‘¾—zŽÐ“d‹C; OUMEMAKERKATAMEI: RPC05T103F; POWERRATING: 100m; QUADMODEL: RES_10K; RESISTANCETOLER: F; SIZECODESMD: 1608; SQ_PART_MODEL: RES_10K; VAL1: 10K(F); VAL2: 100mW; VAL3: RPC05T103F
R22 R44 R66 = R: ADSCNVFLAG: ON; ADSMODELNAME: s_WSHP28182L000FEA; ALLGREEN: N:¢²¸; CDBNAME: K01S001K; CDMASTERCADCELG: KDP100B; COMP: K01S001K; COMPONENTNAME: K01S001K_package; COMPONENTTYPE: 4; FNAPPROVALRESUG: 5:bè(KR[h); FNCANCELLATIONG: 0:Žg—p‰Â; FNENVIRONMANTRG: N:¢²¸; FNLEADFREETHET1GT2GMCTH1: N_N_N; FUNCN: K01S001K; GCOUNT: 1; ICX_PART_MODEL: RES_2M; MAXGCOUNT: 1; MOUNTINGFORMSMD: SMD; NOMINALRESISTAN: 2m; OUMECLASSIFICATION: \ÊÀpÅèïRí; OUMEMAKER: VSH rVFCC^[eNmW[; OUMEMAKERKATAMEI: WSHP28182L000FEA; POWERRATING: 10; QUADMODEL: RES_2M; RESISTANCETOLER: F; SIZECODESMD: OTH; SQ_PART_MODEL: RES_2M; VAL1: 20m(F); VAL2: 10W; VAL3: WSHP28182L000FEA
U?#3 = WAKU_DEF100_0: AUTHOR: g4302510; COMPONENTTYPE: 2; DATE: 2021-10-29; DRAWINGNUMBER: RD021-SCHEMATIC2-02; FUNCTION: U_Phase_Circuit; PAGENUMBER: 001; REVISION: 02; SAVEAREA0: -45080,-4508,463680,304612; SHEETNUMBER: 1/4; TIME: 11:14:07; TITLE: Inverter Application Circuit of the TLP5214A Smart Gate Driver Coupler; UPDATEDATE: 2018/06/19; UPDATETIME: 17:41:12; UPDATEUSER: g4302510
D10 = ZD: COMPONENTTYPE: 4; VAL1: CUZ8V2; VAL2: Toshiba
D12 = SBD: COMPONENTTYPE: 4; VAL1: CUS05F30; VAL2: Toshiba
U?#2 = WAKU_DEF100_0: AUTHOR: g4302510; COMPONENTTYPE: 2; DATE: 2021-10-29; DRAWINGNUMBER: RD021-SCHEMATIC2-02; FUNCTION: V_Phase_Circuit; PAGENUMBER: 002; REVISION: 02; SAVEAREA0: -45080,-4508,463680,304612; SHEETNUMBER: 2/4; TIME: 18:41:07; TITLE: Inverter Application Circuit of the TLP5214A Smart Gate Driver Coupler; UPDATEDATE: 2018/06/19; UPDATETIME: 17:42:26; UPDATEUSER: g4302510
U?#1 = WAKU_DEF100_0: AUTHOR: g4302510; COMPONENTTYPE: 2; DATE: 2021-10-29; DRAWINGNUMBER: RD021-SCHEMATIC2-02; FUNCTION: W_Phase_Circuit; PAGENUMBER: 003; REVISION: 02; SAVEAREA0: -45080,-4508,463680,304612; SHEETNUMBER: 3/4; TIME: 18:43:33; TITLE: Inverter Application Circuit of the TLP5214A Smart Gate Driver Coupler; UPDATEDATE: 2018/06/19; UPDATETIME: 17:50:18; UPDATEUSER: g4302510
C64 = C: ADSCNVFLAG: ON; ADSCOMPONENTNAME: C_1005; ADSMODELNAME: s_JMK105CBJ106MV_F; ALLGREEN: N:¢²¸; CAPACITANCETOLE: M; CDBNAME: K0302583; CDMASTERCADCELG: KC0143; COMP: K0302583; COMPONENTNAME: K0302583_package; COMPONENTTYPE: 4; FNAPPROVALRESUG: 5:bè(KR[h); FNCANCELLATIONG: 0:Žg—p‰Â; FNENVIRONMANTRG: N:¢²¸; FNLEADFREETHET1GT2GMCTH1: N_N_N; FUNCN: K0302583; GCOUNT: 1; ICX_PART_MODEL: CON_10U; MAXGCOUNT: 1; NOMINALCAPACITA: 10u; OUMECLASSIFICATION: ƒZƒ‰ƒ~ƒbƒNƒRƒ“ƒfƒ“ƒT; OUMEMAKER: TYD ‘¾—z—U“d; OUMEMAKERKATAMEI: JMK105CBJ106MV-F; PMPRODUCTSTYPEG: HD1; QUADMODEL: CON_10U; RATEDVOLTAGE: 6.3; SIZECODESMD: 1005; SQ_PART_MODEL: CON_10U; VAL1: 10uF(M); VAL2: 6.3V; VAL3: JMK105CBJ106MV-F
C65 = C: ADSCNVFLAG: ON; ADSCOMPONENTNAME: C_1005; ADSMODELNAME: s_GRM1552C1H102JA01D; ALLGREEN: 0:O[; CAPACITANCETOLE: J; CDBNAME: K0301212; CDMASTERCADCELG: KC0005; COMP: K0301212; COMPONENTNAME: K0301212_package; COMPONENTTYPE: 4; FNAPPROVALRESUG: 5:bè(KR[h); FNCANCELLATIONG: 0:Žg—p‰Â; FNENVIRONMANTRG: 0:Žg—p–³; FNLEADFREETHET1GT2GMCTH1: 3_0_N; FUNCN: K0301212; GANSWERREV: 11; GCOUNT: 1; ICX_PART_MODEL: CON_1N; MAXGCOUNT: 1; NOMINALCAPACITA: 1n; OUMECLASSIFICATION: ƒZƒ‰ƒ~ƒbƒNƒRƒ“ƒfƒ“ƒT; OUMEMAKER: MRT ºc»ì; OUMEMAKERKATAMEI: GRM1552C1H102JA01D; PMPRODUCTSTYPEG: DME-PC1; QUADMODEL: CON_1N; RATEDVOLTAGE: 50; SIZECODESMD: 1005; SQ_PART_MODEL: CON_1N; TEMPCHARACTERI2: CH; VAL1: 1nF(J); VAL2: 50V; VAL3: GRM1552C1H102JA01D
IC19 = U372_1: ACCESSTIME: 0; ADSCNVFLAG: ON; ALLGREEN: N:¢²¸; CDBNAME: K4605651; CDMASTERCADCELG: I81089; COMP: K4605651; COMPONENTNAME: U372_pinAssign_U372_1_function; COMPONENTTYPE: 8; CaptureCellPackProp: U372_1A; FNAPPROVALRESUG: 5:bè(KR[h); FNCANCELLATIONG: 0:Žg—p‰Â; FNENVIRONMANTRG: N:¢²¸; FNLEADFREETHET1GT2GMCTH1: N_N_N; FUNCN: U372_1_function; GCOUNT: 1; KIND: CPU; MAXCLOCKFREQ: 80M; MAXGCOUNT: 1; MEMORYCAPACITY: 0; MOUNTINGFORMSMD: SMD; OUMECLASSIFICATION: CPU/ƒ}ƒCƒRƒ“; OUMEMAKER: TSB “ŒŽÅ; OUMEMAKERKATAMEI: TMPM372FWUG; OUMEPARTTYPE: IC; VAL1: TMPM372FWUG; VAL3: TMPM372FWUG
U?#5 = WAKU_DEF100_0: AUTHOR: g4302510; COMPONENTTYPE: 2; DATE: 2021-10-29; DRAWINGNUMBER: RD021-SCHEMATIC2-02; FUNCTION: MCU; PAGENUMBER: 004; REVISION: 02; SAVEAREA0: -45080,-4508,463680,304612; SHEETNUMBER: 4/4; TIME: 18:48:08; TITLE: Inverter Application Circuit of the TLP5214A Smart Gate Driver Coupler; UPDATEDATE: 2018/06/19; UPDATETIME: 17:45:34; UPDATEUSER: g4302510

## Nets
DGND: C1.1 C2.1 C3.1 C4.1 C6.1 C7.1 C9.1 C10.1 C22.1 C23.1 C24.1 C25.1 C27.1 C28.1 C30.1 C31.1 C43.1 C44.1 C45.1 C46.1 C48.1 C49.1 C51.1 C52.1 C64.1 C65.1 IC1.2 IC2.2 IC3.4 IC4.1 IC4.4 IC5.1 IC5.4 IC6.5 IC7.2 IC8.2 IC9.4 IC10.1 IC10.4 IC11.1 IC11.4 IC12.5 IC13.2 IC14.2 IC15.4 IC16.1 IC16.4 IC17.1 IC17.4 IC18.5 IC19.12 IC19.38 IC19.56 R1.1 R2.1 R12.1 R23.1 R24.1 R34.1 R45.1 R46.1 R56.1
GND: C12.1 C15.1 C18.1 C20.1 C33.1 C36.1 C39.1 C41.1 C54.1 C57.1 C60.1 C62.1 D3.A D5.A D10.A D12.A D17.A D19.A IC5.16 IC6.4 IC11.16 IC12.4 IC17.16 IC18.4 R19.2 R22.1 R41.2 R44.1 R63.2 R66.1
-VEH: C11.2 C13.2 C32.2 C34.2 C53.2 C55.2 IC4.9 IC4.10 IC4.12 IC10.9 IC10.10 IC10.12 IC16.9 IC16.10 IC16.12
-VEL: C12.2 C33.2 C54.2 IC5.9 IC5.10 IC5.12 IC11.9 IC11.10 IC11.12 IC17.9 IC17.10 IC17.12
CS: IC19.63
ENA: IC19.27
ENB: IC19.28
ENZ: IC19.29
HSU_FAULT: IC4.3 IC19.23
HSV_FAULT: IC10.3 IC19.25
HSW_FAULT: IC16.3 IC19.26
LSU_FAULT: IC5.3 IC19.24
LSV_FAULT: IC11.3 IC19.32
LSW_FAULT: IC17.3 IC19.31
PWM_HSU_IN: IC1.1 IC19.4 R1.2
PWM_HSV_IN: IC7.1 IC19.6 R23.2
PWM_HSW_IN: IC13.1 IC19.8 R45.2
PWM_LSU_IN: IC2.1 IC19.5 R2.2
PWM_LSV_IN: IC8.1 IC19.7 R24.2
PWM_LSW_IN: IC14.1 IC19.9 R46.2
SCK: IC19.62
SI: IC19.61
SO: IC19.60
U_Phace: C11.1 C14.1 C19.1 D2.A D4.A D7.C IC4.16 Q1.E Q2.C R20.2
UP_Current: C4.2 C5.2 IC3.6 IC19.46 R3.1
V_Phace: C32.1 C35.1 C40.1 D9.A D11.A D14.C IC10.16 Q3.E Q4.C R42.2
VCH: C15.2 C36.2 C57.2 IC5.13 IC11.13 IC17.13 R13.2 R35.2 R57.2
VCL: C1.2 C2.2 C3.2 C6.2 C7.2 C10.2 C22.2 C23.2 C24.2 C27.2 C28.2 C31.2 C43.2 C44.2 C45.2 C48.2 C49.2 C52.2 C64.2 C65.2 IC1.5 IC2.5 IC3.7 IC4.2 IC5.2 IC6.8 IC7.5 IC8.5 IC9.7 IC10.2 IC11.2 IC12.8 IC13.5 IC14.5 IC15.7 IC16.2 IC17.2 IC18.8 IC19.13 IC19.36 IC19.42 IC19.57 R6.2 R7.2 R11.2 R28.2 R29.2 R33.2 R50.2 R51.2 R55.2
VDH: C18.2 C39.2 C60.2 IC6.1 IC12.1 IC18.1
VP: D6.C D13.C D20.C Q1.C Q3.C Q5.C
VP_Current: C25.2 C26.2 IC9.6 IC19.47 R25.1
W_Phace: C53.1 C56.1 C61.1 D16.A D18.A D21.C IC16.16 Q5.E Q6.C R64.2
WP_Current: C46.2 C47.2 IC15.6 IC19.48 R47.1
N01331: C5.1 IC3.2 R3.2 R10.1
N01375: IC4.6 IC4.7 R6.1
N01391: IC5.11 R14.1
N01423: IC5.5 IC5.8 R5.2
N01441: C21.1 IC6.3 R19.1
N01461: IC6.6 R10.2
N01475: D6.A R16.2
N01491: C21.2 IC6.2 R18.1
N01507: IC4.5 IC4.8 R4.2
N01517: IC6.7 R9.2
N01591: D1.A R13.1
N01601: IC5.6 IC5.7 R7.1
N01607: D7.A R17.2
N01611: IC4.11 R15.1
N01627: Q2.E R18.2 R21.2 R22.2
N01637: Q2.G R14.2 R21.1
N01647: Q1.G R15.2 R20.1
N01703: C13.1 C14.2 D1.C IC4.13
N01811: C8.2 IC3.3 R8.1 R9.1
N01827: C8.1 C9.2 R8.2 R11.1 R12.2
N01907: C19.2 D2.C D4.C IC4.14 R16.1
N01923: C20.2 D3.C D5.C IC5.14 R17.1
N03188: Q3.G R37.2 R42.1
N03206: IC11.6 IC11.7 R29.1
N03214: Q4.G R36.2 R43.1
N03224: Q4.E R40.2 R43.2 R44.2
N03238: D8.A R35.1
N03242: IC10.11 R37.1
N03250: C34.1 C35.2 D8.C IC10.13
N03268: D14.A R39.2
N03272: C42.2 IC12.2 R40.1
N03284: D13.A R38.2
N03288: C41.2 D10.C D12.C IC11.14 R39.1
N03342: C26.1 IC9.2 R25.2 R32.1
N03394: IC10.5 IC10.8 R26.2
N03404: IC12.7 R31.2
N03442: IC10.6 IC10.7 R28.1
N03508: IC11.11 R36.1
N03552: C29.1 C30.2 R30.2 R33.1 R34.2
N03570: IC11.5 IC11.8 R27.2
N03600: C29.2 IC9.3 R30.1 R31.1
N03616: IC12.6 R32.2
N03634: C42.1 IC12.3 R41.1
N03734: C40.2 D9.C D11.C IC10.14 R38.1
N05000: Q5.G R59.2 R64.1
N05018: IC17.6 IC17.7 R51.1
N05026: Q6.G R58.2 R65.1
N05036: Q6.E R62.2 R65.2 R66.2
N05050: D15.A R57.1
N05054: IC16.11 R59.1
N05062: C55.1 C56.2 D15.C IC16.13
N05080: D21.A R61.2
N05084: C63.2 IC18.2 R62.1
N05096: D20.A R60.2
N05100: C62.2 D17.C D19.C IC17.14 R61.1
N05154: C47.1 IC15.2 R47.2 R54.1
N05206: IC16.5 IC16.8 R48.2
N05216: IC18.7 R53.2
N05254: IC16.6 IC16.7 R50.1
N05320: IC17.11 R58.1
N05364: C50.1 C51.2 R52.2 R55.1 R56.2
N05382: IC17.5 IC17.8 R49.2
N05412: C50.2 IC15.3 R52.1 R53.1
N05428: IC18.6 R54.2
N05446: C63.1 IC18.3 R63.1
N05546: C61.2 D16.C D18.C IC16.14 R60.1
N30379: IC2.4 R5.1
N30380: IC1.4 R4.1
N30819: IC7.4 R26.1
N30820: IC8.4 R27.1
N31251: IC13.4 R48.1
N31252: IC14.4 R49.1

Not connected (* = marked no-connect by the designer): IC1 3; IC2 3; IC3 1 5 8; IC4 15; IC5 15; IC7 3; IC8 3; IC9 1 5 8; IC10 15; IC11 15; IC13 3; IC14 3; IC15 1 5 8; IC16 15; IC17 15; IC19 1 2 3 10 11 14 15 16 17 18 19 20 21 22 30 33 34 35 37 39 40 41 43 44 45 49 50 51 52 53 54 55 58 59 64

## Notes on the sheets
sheet 1
- MCU
  Reference Example
- From the Motor
- MCU control from
- the main controller
sheet 5
- VCL
- VCH
- VP
- PWM
- TC7SZ14F
- TLP5214A
- GT30J341
- -VEH
- U_Phase
- VCL
- VCH
- PWM
- TC7SZ14F
- TLP5214A
- GT30J341
- -VEL
- VCL
- VCL
- VDH
- U_Current
- OPA237
- TLP7820
- R
- VCL
- VCH
- VP
- PWM
- TC7SZ14F
- TLP5214A
- GT30J341
- Main Controller
- -VEH
- V_Phase
- VCL
- VCH
- MCU
- PWM
- SPI
- TC7SZ14F
- TLP5214A
- GT30J341
- -VEL
- VCL
- VCL
- VDH
- MOTOR
- V_Current
- R
- OPA237
- TLP7820
- VP
- VCL
- VCH
- PWM
- TC7SZ14F
- TLP5214A
- GT30J341
- -VEH
- VCL
- VCH
- PWM
- W_Phase
- TC7SZ14F
- TLP5214A
- GT30J341
- -VEL
- VCL
- VCL
- VDH
- W_Current
- R
- OPA237
- TLP7820
- Encoder Signal
